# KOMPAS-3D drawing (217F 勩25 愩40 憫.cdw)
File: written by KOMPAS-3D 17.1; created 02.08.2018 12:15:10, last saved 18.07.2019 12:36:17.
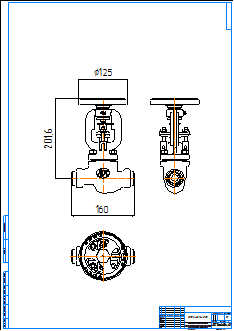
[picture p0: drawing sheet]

Sheet 1: A1, portrait

Title block, sheet 1: name: 217F Ду25 Ру40 СС; material: Внимание! Данный продукт является объектом авторского права ООО «Торговый Дом АДЛ». / Запрещается изменение, копирование, распространение / (в том числе путем копирования на другие сайты и ресурсы в Интернете) / или любое иное использование информации и объектов без предварительного / согласия правообладателя (ООО «Торговый Дом АДЛ»).; sheets: 1; organisation: ООО "Торговый дом АДЛ"; sheet format: A1; stored path: \\adlc.lan\data\АДЛ_ПКД\3D-модели\Поставщики\Zetkama\Вентили\217F\KOMPAS 2D\217F Ду25 Ру40 СС.cdw

Views: Вид 1, Проекционный вид 2, Проекционный вид 3
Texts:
  kka
  adl
Dimensions and other numbers on the sheet: 160; 201,6; 125; 1:1; 1; 217F Ду25 Ру40 СС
